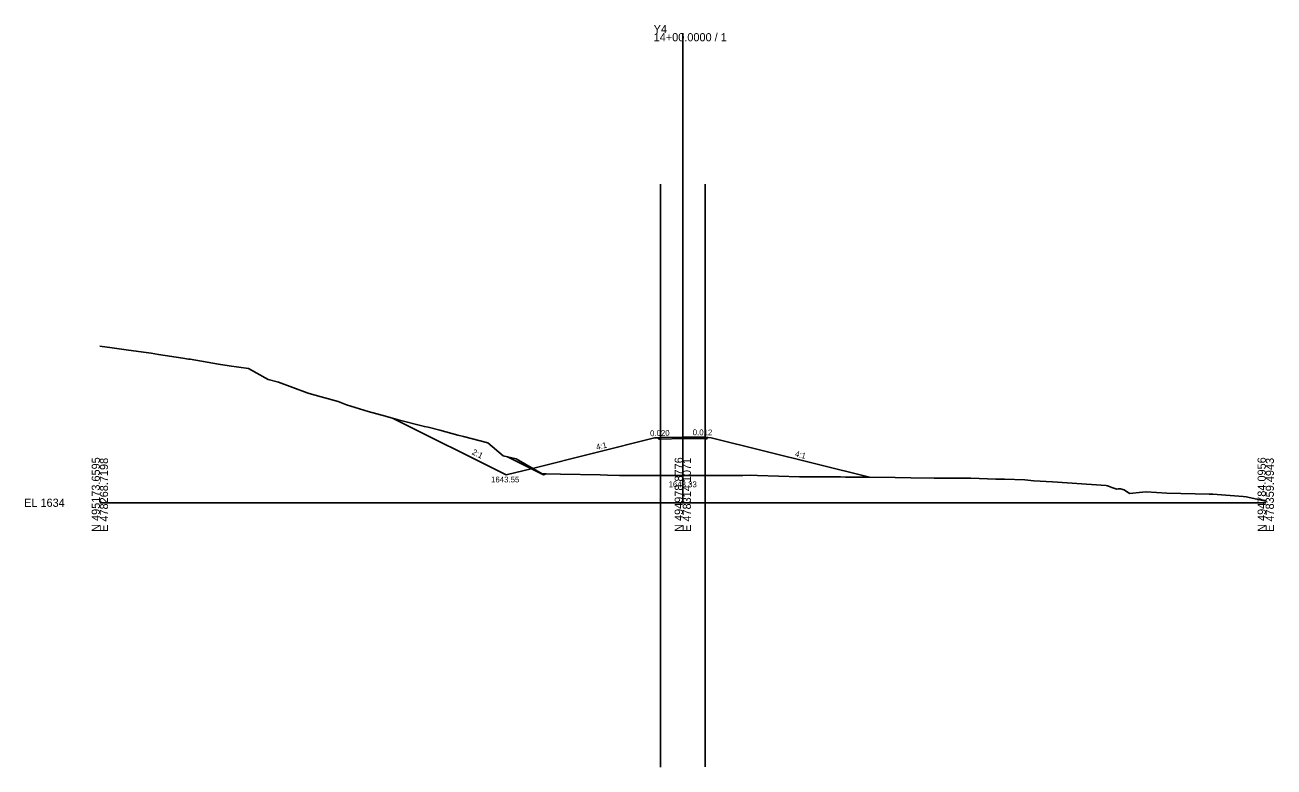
# Model space of a CAD drawing. Extents: x -26 to 403, y -10 to 5108.
# Drawn here: x -25.7 to 402.8, y 3909.3 to 4164 of the extents above; entities that cross this region are included whole.
import ezdxf

# ---------------------------------------------------------------- set-up
doc = ezdxf.new("R2010")
doc.units = 0
for name, color, linetype in [('Exist Cross Section Cell', 7, 'Continuous'), ('Exist XS Center Line Elevation Label', 7, 'Continuous'), ('Exist XS Ground Line', 7, 'Continuous'), ('Prop XS DDE Earthwork Shape', 7, 'Continuous'), ('Prop XS DDE Elevations', 7, 'Continuous'), ('Prop XS DDE Slope Text', 7, 'Continuous'), ('Prop XS Dump Level', 7, 'Continuous'), ('Prop XS Earthwork Shape', 7, 'Continuous'), ('Prop XS EOT Tick Mark', 7, 'Continuous'), ('Prop XS Finish Grade', 7, 'Continuous'), ('Prop XS Finish Grade Earthwork', 7, 'Continuous'), ('Prop XS Finish Grade Pavement', 7, 'Continuous'), ('Prop XS Pvmt Edge Slope', 7, 'Continuous'), ('Prop XS SE Text', 7, 'Continuous'), ('Prop XS Shoulder Borrow Shape', 7, 'Continuous'), ('Prop XS Side Slope Text', 7, 'Continuous'), ('Prop XS Subgrade Earthwork', 7, 'Continuous'), ('Scratch_Level_1', 7, 'Continuous'), ('Scratch_Level_2', 7, 'Continuous')]:
    doc.layers.add(name, color=color, linetype=linetype)

msp = doc.modelspace()

# ---------------------------------------------------------------- linework, layer by layer
at = {"layer": 'Exist Cross Section Cell'}
for p, q in [((200, 4000), (200, 4161.16)), ((0, 4000), (200, 4000)), ((200, 4000), (400, 4000))]:
    msp.add_line(p, q, dxfattribs=at)
at = {"layer": 'Exist XS Ground Line'}
msp.add_lwpolyline([(0, 4053.72), (4.22, 4053.21), (9.88, 4052.41), (17.61, 4051.31), (20.15, 4050.89), (28.5, 4049.63), (30.42, 4049.32), (31, 4049.24), (40.69, 4047.58), (44.39, 4047.04), (50.96, 4046.08), (57.78, 4042.3), (61.23, 4041.38), (71.17, 4037.7), (71.5, 4037.61), (72.57, 4037.32), (81.77, 4034.71), (84.56, 4033.62), (92.04, 4031.33), (97.95, 4029.72), (102.31, 4028.5), (111.34, 4026.12), (112.58, 4025.92), (116.65, 4024.86), (122.85, 4023.18), (124.73, 4022.72), (133.12, 4020.62), (138.33, 4016.08), (142.82, 4015.02), (151.7, 4009.89), (158.07, 4009.83), (171.65, 4009.57), (174.2, 4009.47), (178.29, 4009.41), (184.47, 4009.3), (191.68, 4009.31), (194.74, 4009.31), (196.64, 4009.32), (200, 4009.33), (206.62, 4009.34), (210.84, 4009.32), (220.61, 4009.39), (223.39, 4009.51), (225.58, 4009.37), (240.05, 4008.95), (240.64, 4008.93), (245.86, 4008.86), (254.15, 4008.85), (255.78, 4008.83), (258.36, 4008.79), (272.88, 4008.63), (278.21, 4008.6), (286.28, 4008.49), (288.42, 4008.46), (292.94, 4008.46), (297.44, 4008.43), (298.8, 4008.39), (307.34, 4008.12), (310.42, 4008.04), (317.34, 4007.84), (320.41, 4007.58), (326.85, 4007.17), (345.25, 4005.97), (345.66, 4005.83), (346, 4005.68), (347.19, 4005.24), (348.93, 4004.7), (349.32, 4004.75), (349.71, 4004.8), (350.21, 4004.77), (351.46, 4004.48), (353.21, 4003.17), (357.7, 4003.64), (359, 4003.73), (366.08, 4003.26), (380.61, 4002.92), (381.34, 4002.91), (381.89, 4002.91), (392.3, 4002.14), (393.24, 4002.03), (400, 4000.52)], dxfattribs=at)
at = {"layer": 'Prop XS DDE Earthwork Shape'}
for points in [[(148.39, 4011.8), (139.37, 4009.55), (100.41, 4029.03), (102.31, 4028.5), (111.34, 4026.12), (112.58, 4025.92), (116.65, 4024.86), (122.85, 4023.18), (124.73, 4022.72), (133.12, 4020.62), (138.33, 4016.08), (142.82, 4015.02)], [(142.82, 4015.02), (151.7, 4009.89), (153.17, 4009.87), (152.19, 4009.55), (139.85, 4015.72)], [(151.7, 4009.89), (153.17, 4009.87), (152.19, 4009.55), (139.85, 4015.72), (142.82, 4015.02)]]:
    msp.add_lwpolyline(points, close=True, dxfattribs=at)
at = {"layer": 'Prop XS Dump Level'}
for p, q in [((192.3, 4022.41), (200, 4022.56)), ((200, 4022.56), (207.7, 4022.47))]:
    msp.add_line(p, q, dxfattribs=at)
at = {"layer": 'Prop XS Earthwork Shape'}
for points in [[(100.41, 4029.03), (102.31, 4028.5), (111.34, 4026.12), (112.58, 4025.92), (116.65, 4024.86), (122.85, 4023.18), (124.73, 4022.72), (133.12, 4020.62), (138.33, 4016.08), (142.82, 4015.02), (148.39, 4011.8), (139.37, 4009.55)], [(148.39, 4011.8), (151.7, 4009.89), (158.07, 4009.83), (171.65, 4009.57), (174.2, 4009.47), (178.29, 4009.41), (184.47, 4009.3), (191.68, 4009.31), (194.74, 4009.31), (196.64, 4009.32), (200, 4009.33), (206.62, 4009.34), (210.84, 4009.32), (220.61, 4009.39), (223.39, 4009.51), (225.58, 4009.37), (240.05, 4008.95), (240.64, 4008.93), (245.86, 4008.86), (254.15, 4008.85), (255.78, 4008.83), (258.36, 4008.79), (264.09, 4008.73), (209.71, 4022.32), (208.73, 4022.39), (208.25, 4021.92), (207.7, 4021.92), (200, 4022.02), (192.3, 4021.87), (191.74, 4021.85), (191.27, 4022.33), (190.29, 4022.25)]]:
    msp.add_lwpolyline(points, close=True, dxfattribs=at)
at = {"layer": 'Prop XS EOT Tick Mark'}
for p, q in [((192.3, 4022.41), (192.3, 4023.41)), ((207.7, 4022.47), (207.7, 4023.47))]:
    msp.add_line(p, q, dxfattribs=at)
at = {"layer": 'Prop XS Finish Grade'}
for p, q in [((192.3, 4022.41), (191.27, 4022.33)), ((207.7, 4022.47), (208.73, 4022.39))]:
    msp.add_line(p, q, dxfattribs=at)
at = {"layer": 'Prop XS Finish Grade Earthwork'}
for p, q in [((139.37, 4009.55), (100.41, 4029.03)), ((190.29, 4022.25), (148.39, 4011.8)), ((191.27, 4022.33), (190.29, 4022.25)), ((208.73, 4022.39), (209.71, 4022.32)), ((209.71, 4022.32), (264.09, 4008.73)), ((148.39, 4011.8), (139.37, 4009.55))]:
    msp.add_line(p, q, dxfattribs=at)
at = {"layer": 'Prop XS Finish Grade Pavement'}
for p, q in [((192.3, 4022.41), (200, 4022.56)), ((200, 4022.56), (207.7, 4022.47))]:
    msp.add_line(p, q, dxfattribs=at)
at = {"layer": 'Prop XS Pvmt Edge Slope'}
for p, q in [((192.3, 4022.41), (191.74, 4021.85)), ((207.7, 4022.47), (208.25, 4021.92))]:
    msp.add_line(p, q, dxfattribs=at)
at = {"layer": 'Prop XS Shoulder Borrow Shape'}
for points in [[(192.3, 4022.41), (191.27, 4022.33), (191.74, 4021.85)], [(207.7, 4022.47), (208.73, 4022.39), (208.25, 4021.92)]]:
    msp.add_lwpolyline(points, close=True, dxfattribs=at)
at = {"layer": 'Prop XS Subgrade Earthwork'}
for p, q in [((191.74, 4021.85), (191.27, 4022.33)), ((192.3, 4021.87), (191.74, 4021.85)), ((200, 4022.02), (192.3, 4021.87)), ((207.7, 4021.92), (200, 4022.02)), ((207.7, 4021.92), (208.25, 4021.92)), ((208.25, 4021.92), (208.73, 4022.39))]:
    msp.add_line(p, q, dxfattribs=at)
at = {"layer": 'Scratch_Level_1'}
for p, q in [((192.3, 4109.31), (192.3, 3909.31)), ((207.7, 4109.34), (207.7, 3909.34))]:
    msp.add_line(p, q, dxfattribs=at)
at = {"layer": 'Scratch_Level_2'}
msp.add_lwpolyline([(139.37, 4009.55), (100.41, 4029.03), (102.31, 4028.5), (111.34, 4026.12), (112.58, 4025.92), (116.65, 4024.86), (122.85, 4023.18), (124.73, 4022.72), (133.12, 4020.62), (138.33, 4016.08), (142.82, 4015.02), (148.39, 4011.8)], close=True, dxfattribs=at)

# ---------------------------------------------------------------- texts
at = {"layer": 'Exist Cross Section Cell'}
for s, p in [('Y4', (190, 4161.16)), ('14+00.0000 / 1', (190, 4158.36)), ('EL 1634', (-26, 3998.6))]:
    msp.add_text(s, height=2.8, dxfattribs=at).set_placement(p)
for s, p in [('N 495173.6595', (0, 3990)), ('N 494978.8776', (200, 3990)), ('N 494784.0956', (400, 3990)), ('E 478268.7198', (2.8, 3990)), ('E 478314.1071', (202.8, 3990)), ('E 478359.4943', (402.8, 3990))]:
    msp.add_text(s, height=2.8, rotation=90, dxfattribs=at).set_placement(p)
at = {"layer": 'Exist XS Center Line Elevation Label'}
msp.add_text('1643.33', height=2, dxfattribs=at).set_placement((195.13, 4005.33))
at = {"layer": 'Prop XS DDE Elevations'}
msp.add_text('1643.55', height=2, dxfattribs=at).set_placement((134.23, 4006.98))
at = {"layer": 'Prop XS DDE Slope Text'}
msp.add_text('2:1', height=2, rotation=333.4355, dxfattribs=at).set_placement((127.48, 4016.74))
at = {"layer": 'Prop XS Dump Level'}
for p in [(190.29, 4022.21), (209.71, 4022.28)]:
    msp.add_text('Case1', height=0.04, dxfattribs=at).set_placement(p)
at = {"layer": 'Prop XS SE Text'}
for s, rotation, p in [('0.020', 1.1458, (188.79, 4022.84)), ('0.012', 359.2919, (203.4, 4023.19))]:
    msp.add_text(s, height=2, rotation=rotation, dxfattribs=at).set_placement(p)
at = {"layer": 'Prop XS Side Slope Text'}
for rotation, p in [(14.0094, (170.51, 4018.06)), (345.9638, (238.35, 4015.93))]:
    msp.add_text('4:1', height=2, rotation=rotation, dxfattribs=at).set_placement(p)

doc.saveas('drawing.dxf')
